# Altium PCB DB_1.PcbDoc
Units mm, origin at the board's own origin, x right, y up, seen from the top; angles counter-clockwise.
Board outline 57.15 x 76.2 mm, 4 copper layers (Top Layer, Signal Layer 1, Ground, Bottom Layer), stack 0.778 mm thick; 61 components, 63 nets, 348 pads, 125 vias.
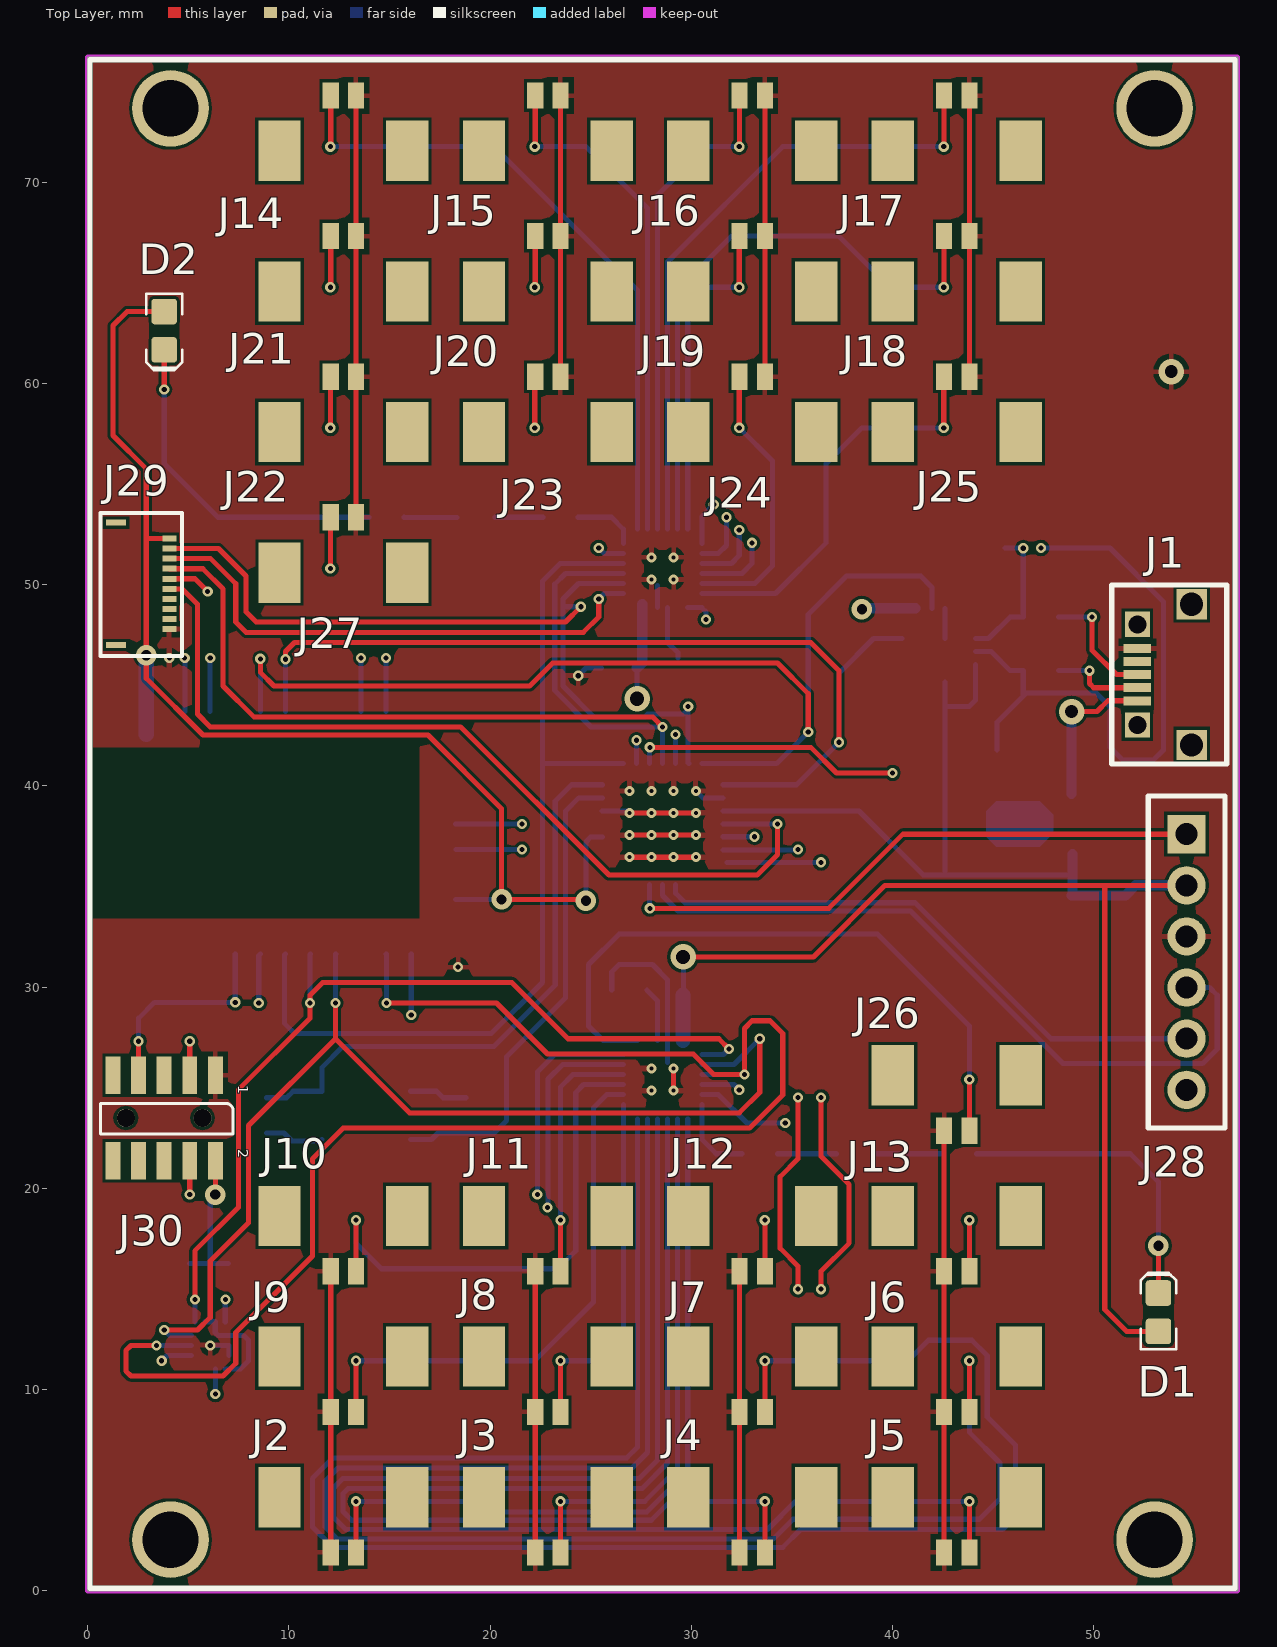
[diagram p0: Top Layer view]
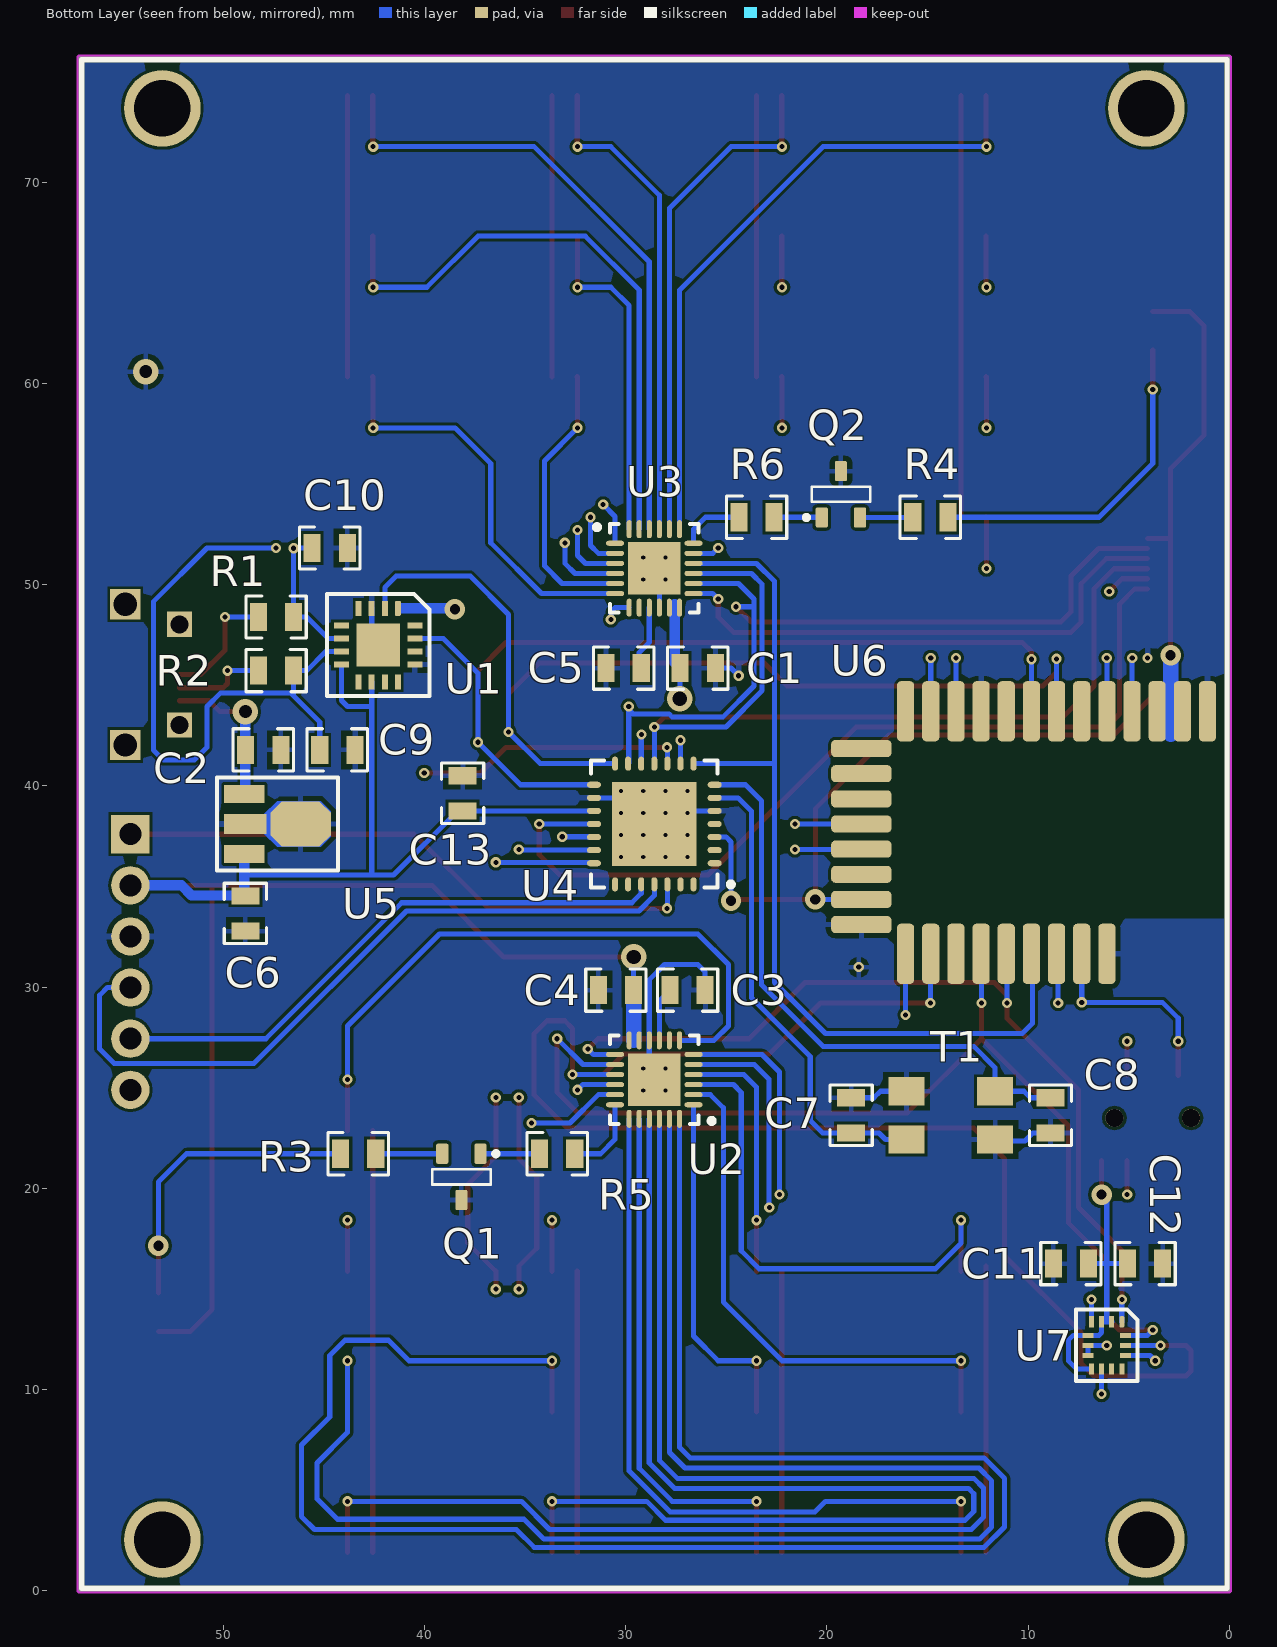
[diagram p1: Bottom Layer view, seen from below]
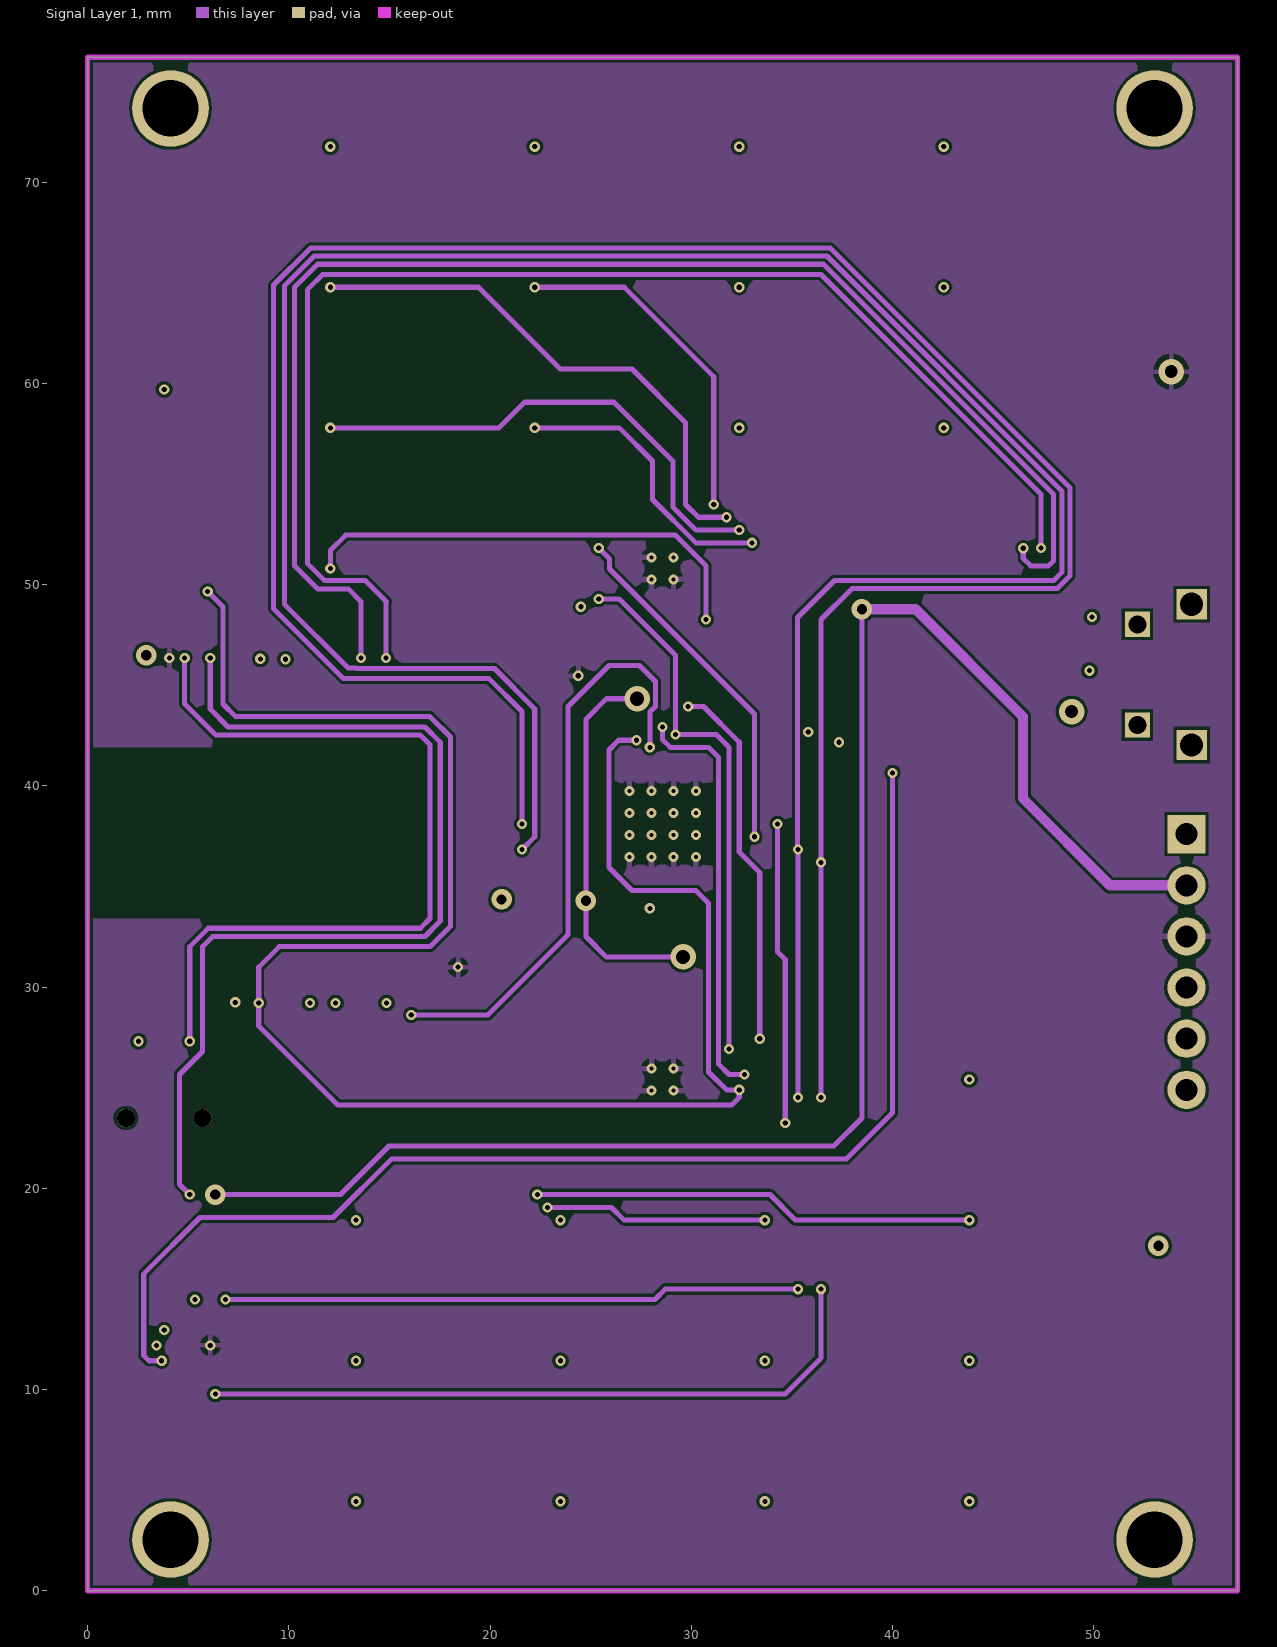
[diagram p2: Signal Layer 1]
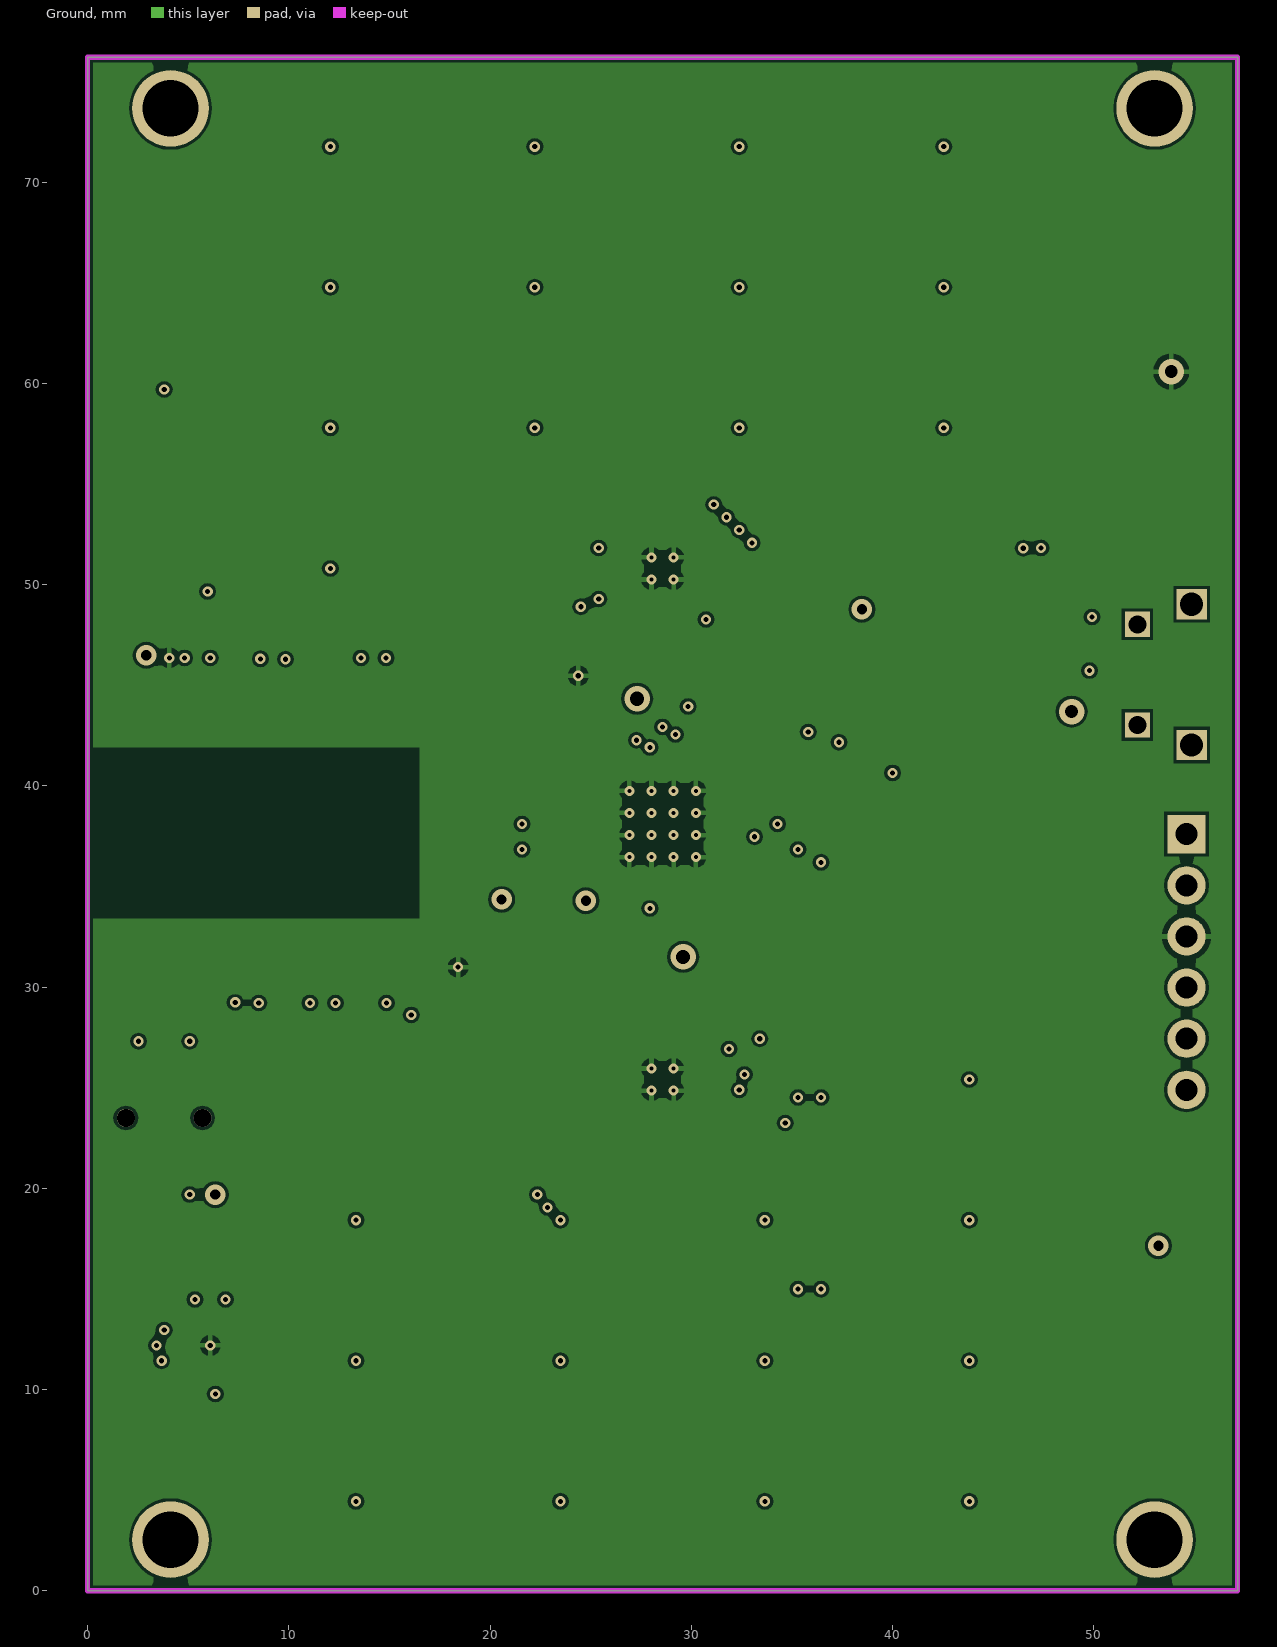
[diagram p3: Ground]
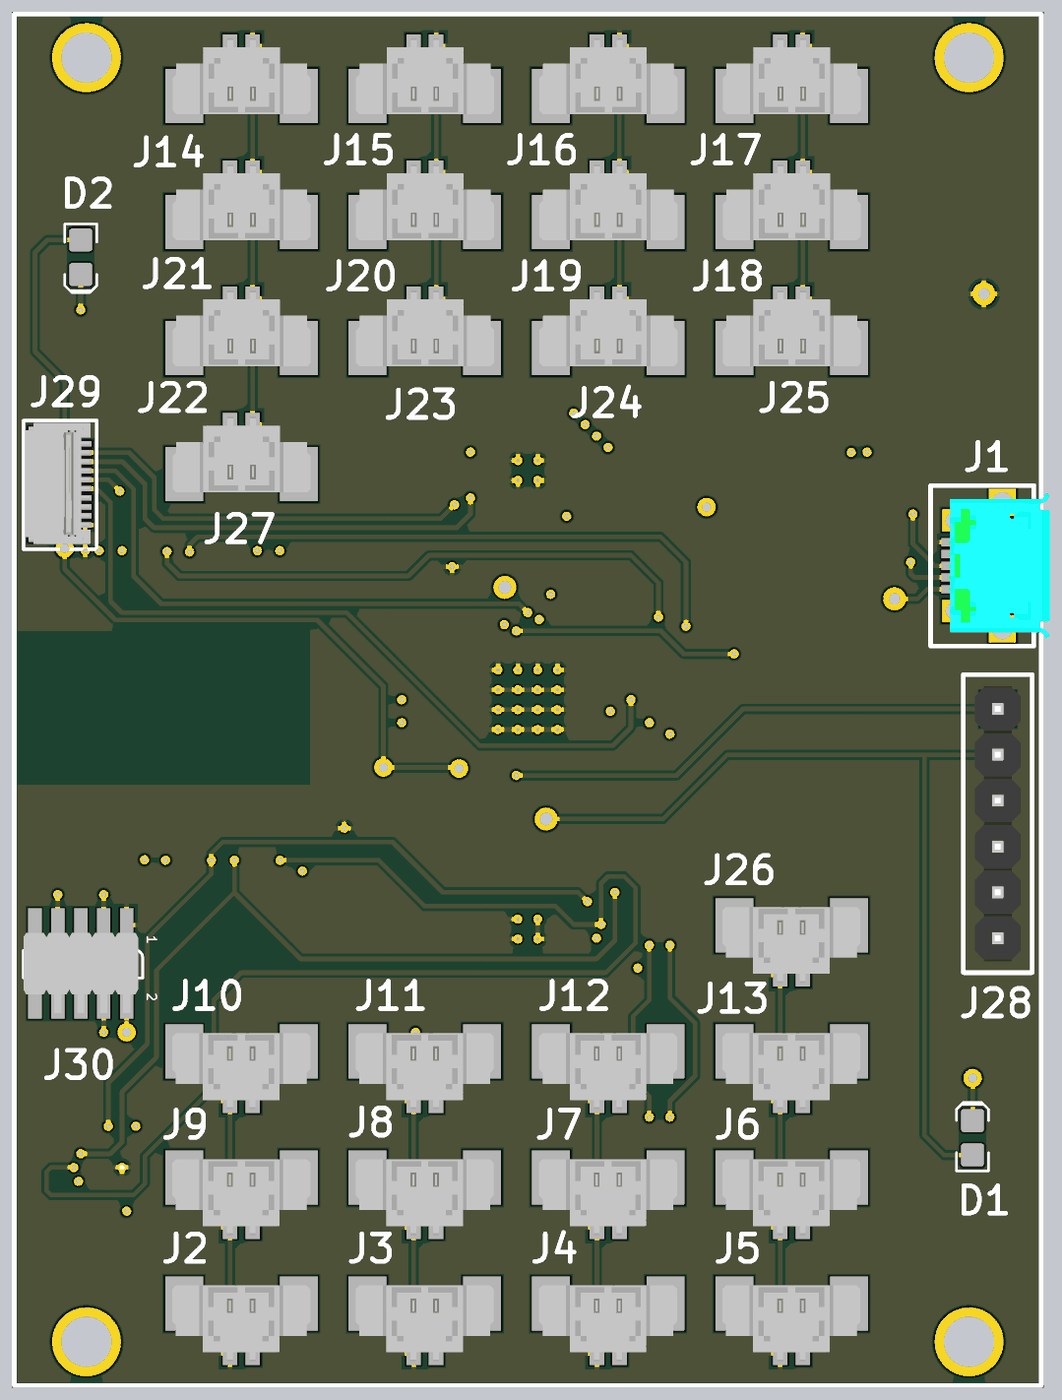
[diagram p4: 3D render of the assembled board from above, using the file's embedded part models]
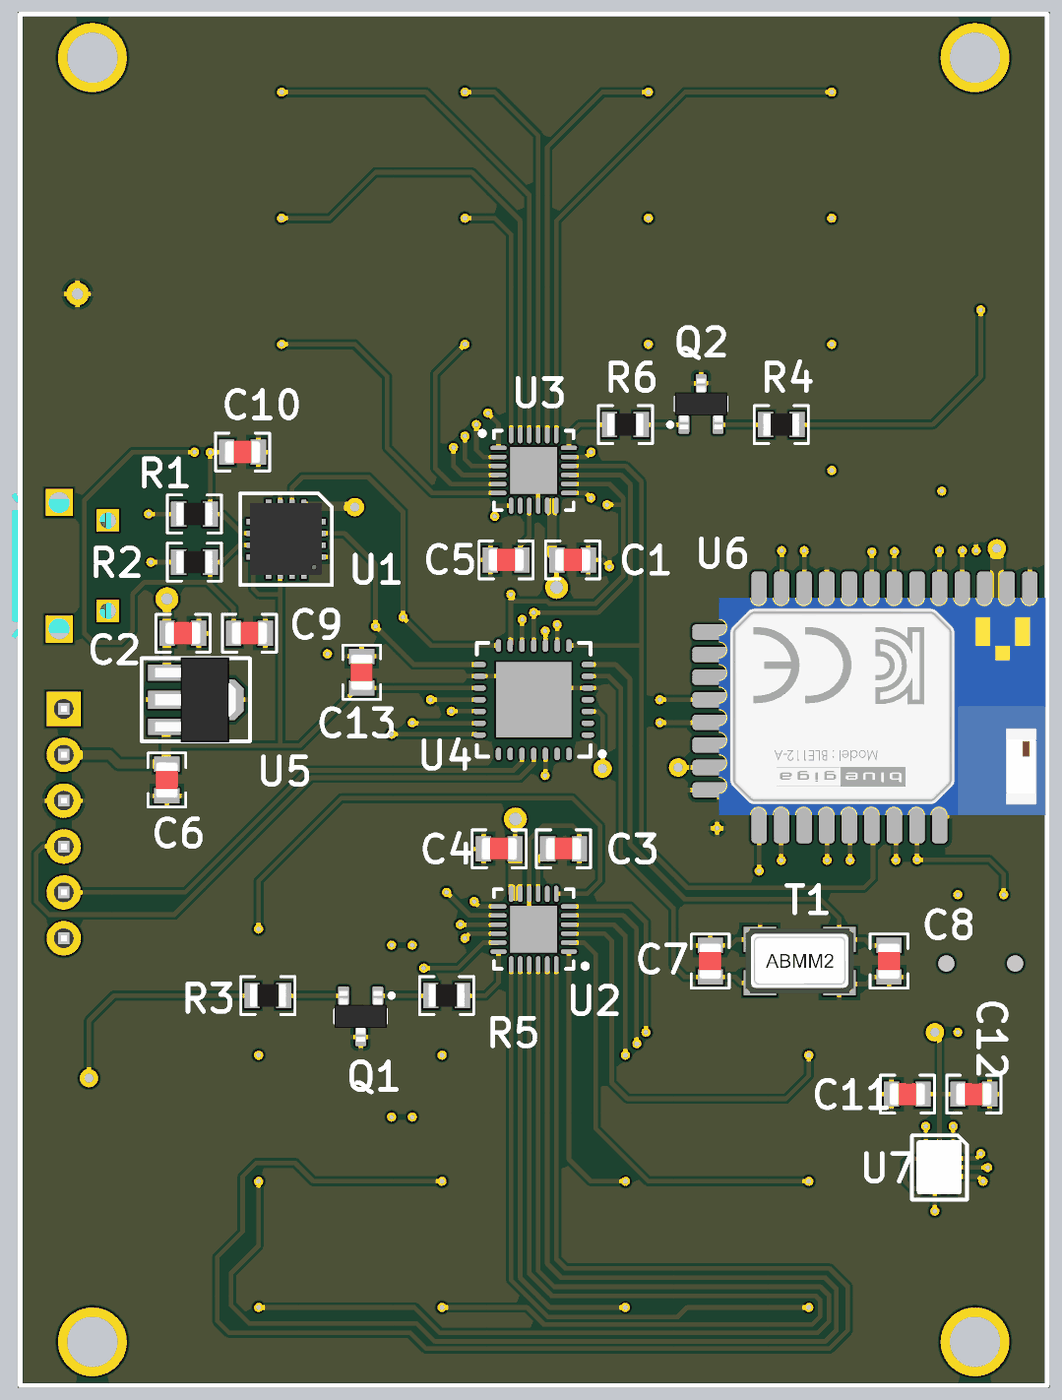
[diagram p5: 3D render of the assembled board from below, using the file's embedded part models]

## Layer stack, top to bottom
Top Solder: solder mask 0.0102, Solder Resist, Dk 3.5
Top Layer: signal copper 0.0356
Dielectric 1: core 0.254, FR-4, Dk 4.2
Signal Layer 1: signal copper 0.036
Dielectric 3: prepreg 0.127, Dk 4.2
Ground: signal copper 0.036
Dielectric 2: core 0.254, Dk 4.2
Bottom Layer: signal copper 0.0356
Bottom Solder: solder mask 0.0102, Solder Resist, Dk 3.5

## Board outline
0,0 57.15,0 57.15,76.2 0,76.2

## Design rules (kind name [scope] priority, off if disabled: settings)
Clearance [All] p1: gap=0.152
HoleSize [All] p1: absolutevalues=TRUE maxlimit=5.08 minlimit=0.025 maxpercent=80.000 minpercent=20.000
HoleToHoleClearance [All] p1: gap=0.152 allowstackedmicrovias=TRUE
MinimumSolderMaskSliver [All] p1: minsoldermaskwidth=0.152
PolygonConnect [All] p1: connectstyle=Relief reliefconductorwidth=0.254 reliefentries=4 polygonreliefangle="90 Angle" airgapwidth=0.254
RoutingVias [All] p1: holewidth=0.711 width=1.27 viastyle="Through Hole" minholewidth=0.203 minwidth=0.406 maxholewidth=0.711 maxwidth=1.27
SilkToSilkClearance [All] p1: silktosilkclearance=0.152
SilkToSolderMaskClearance [IsPad] p1: minsilkscreentomaskgap=0.152 clearancetoexposedcopper=TRUE
SolderMaskExpansion [All] p1: expansion=0.102
Width [All] p1: maxlimit=1.27 minlimit=0.152 preferedwidth=0.254
25 further rules are at their usual default settings.

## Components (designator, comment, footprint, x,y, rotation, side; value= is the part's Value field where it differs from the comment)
C1 "0.1µF" CAP-0805(2012)-R 26.416,45.847 r180 bottom
C2 "0.33µF" CAP-0805(2012)-R 48.006,41.783 r180 bottom
C3 "10000pF" CAP-0805(2012)-R 26.924,29.845 r180 bottom
C4 "0.1µF" CAP-0805(2012)-R 30.48,29.845 r0 bottom
C5 "10000pF" CAP-0805(2012)-R 30.099,45.847 r0 bottom
C6 "0.1µF" CAP-0805(2012)-R 48.895,33.655 r270 bottom
C7 "18pF" CAP-0805(2012)-R 18.796,23.622 r90 bottom
C8 "18pF" CAP-0805(2012)-R 8.89,23.622 r270 bottom
C9 "47pF" CAP-0805(2012)-R 44.323,41.783 r0 bottom
C10 "47pF" CAP-0805(2012)-R 44.704,51.816 r0 bottom
C11 "0.1µF" CAP-0805(2012)-R 7.874,16.256 r180 bottom
C12 "10000pF" CAP-0805(2012)-R 4.191,16.256 r0 bottom
C13 "0.1µF" CAP-0805(2012)-R 38.1,39.624 r90 bottom
D1 "YELLOW" LED-0805-A 53.213,13.843 r90 top
D2 "YELLOW" LED-0805-A 3.81,62.611 r270 top
J1 "USB" USB_CONNECTOR_5P_MICRO_USB_FCI 52.164,45.522 r90 top
J2 "Header 2 pin" WM7606CT-ND 13.335,1.905 r180 top
J3 "Header 2 pin" WM7606CT-ND 23.495,1.905 r180 top
J4 "Header 2 pin" WM7606CT-ND 33.655,1.905 r180 top
J5 "Header 2 pin" WM7606CT-ND 43.815,1.905 r180 top
J6 "Header 2 pin" WM7606CT-ND 43.815,8.89 r180 top
J7 "Header 2 pin" WM7606CT-ND 33.655,8.89 r180 top
J8 "Header 2 pin" WM7606CT-ND 23.495,8.89 r180 top
J9 "Header 2 pin" WM7606CT-ND 13.335,8.89 r180 top
J10 "Header 2 pin" WM7606CT-ND 13.335,15.875 r180 top
J11 "Header 2 pin" WM7606CT-ND 23.495,15.875 r180 top
J12 "Header 2 pin" WM7606CT-ND 33.655,15.875 r180 top
J13 "Header 2 pin" WM7606CT-ND 43.815,15.875 r180 top
J14 "Header 2 pin" WM7606CT-ND 12.085,74.295 r0 top
J15 "Header 2 pin" WM7606CT-ND 22.245,74.295 r0 top
J16 "Header 2 pin" WM7606CT-ND 32.405,74.295 r0 top
J17 "Header 2 pin" WM7606CT-ND 42.565,74.295 r0 top
J18 "Header 2 pin" WM7606CT-ND 42.565,67.31 r0 top
J19 "Header 2 pin" WM7606CT-ND 32.405,67.31 r0 top
J20 "Header 2 pin" WM7606CT-ND 22.245,67.31 r0 top
J21 "Header 2 pin" WM7606CT-ND 12.085,67.31 r0 top
J22 "Header 2 pin" WM7606CT-ND 12.085,60.325 r0 top
J23 "Header 2 pin" WM7606CT-ND 22.245,60.325 r0 top
J24 "Header 2 pin" WM7606CT-ND 32.405,60.325 r0 top
J25 "Header 2 pin" WM7606CT-ND 42.565,60.325 r0 top
J26 "Header 2 pin" WM7606CT-ND 43.815,22.86 r180 top
J27 "Header 2 pin" WM7606CT-ND 12.085,53.34 r0 top
J28 "Header 6 pin" HEADER-6-100MIL 54.61,37.592 r270 top
J29 "Header 10 pin" MOLEX-503480-1000 4.064,52.284 r270 top
J30 "GRPB052VWQP-RC" GRPB052VWQP-RC 1.27,25.616 r270 top
Q1 "Value" SOT23-3 38.161,20.567 r90 bottom
Q2 "Value" SOT23-3 19.304,54.483 r270 bottom
R1 "27" R-0805(2012)-R 47.371,48.387 r180 bottom
R2 "27" R-0805(2012)-R 47.371,45.72 r180 bottom
R3 "30" R-0805(2012)-R 43.293,21.717 r0 bottom
R4 "30" R-0805(2012)-R 14.859,53.34 r180 bottom
R5 "1k" R-0805(2012)-R 33.401,21.717 r180 bottom
R6 "1k" R-0805(2012)-R 23.495,53.34 r180 bottom
T1 "8MHz" CRYSTAL-8MHZ 13.843,23.622 r180 bottom
U1 "FT230XQ-R" QFN-16 42.291,46.99 r270 bottom
U2 "ADI-AD7147" LFCSP_WQ 28.575,25.4 r0 bottom
U3 "ADI-AD7147" LFCSP_WQ 28.575,50.8 r180 bottom
U4 "PIC18F25K80" MCHP-QFN-S-MM28_N 28.575,38.1 r0 bottom
U5 "L78L33ACUTR" SOT89-3 47.295,38.1 r180 bottom
U6 "BLE112-A-V1" BLE112-A-V1 18.288,43.7 r270 bottom
U7 "LSM6DS3H" LGA-14 6.096,12.192 r270 bottom

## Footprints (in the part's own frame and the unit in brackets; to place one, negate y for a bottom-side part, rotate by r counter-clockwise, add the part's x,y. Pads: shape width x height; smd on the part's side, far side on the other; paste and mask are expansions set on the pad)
BLE112-A-V1 [mm] "CLASS 2 BLTOOTH 4.0 MODULE"
  rrect50% 3x0.85 smd: 1(0,17.2) 2(0,15.95) 3(0,14.7) 4(0,13.45) 5(0,12.2) 6(0,10.95) 7(0,9.7) 8(0,8.45) 9(0,7.2) 10(0,5.95) 11(0,4.7) 12(0,3.45) 13(0,2.2) 22(12.05,2.2) 23(12.05,3.45) 24(12.05,4.7) 25(12.05,5.95) 26(12.05,7.2) 27(12.05,8.45) 28(12.05,9.7) 29(12.05,10.95) 30(12.05,12.2)
  rrect50% 0.85x3 smd: 14(1.85,0) 15(3.1,0) 16(4.35,0) 17(5.6,0) 18(6.85,0) 19(8.1,0) 20(9.35,0) 21(10.6,0)
  body extent -0.06,-0.03 11.99,18.07, height 2.3
CAP-0805(2012)-R [mm] "Capacitor 0805(2012) Reflow"
  rect 0.85x1.4 smd: 1(-0.875,0) 2(0.875,0)
  silkscreen extent -1.5,-1.05 1.5,1.05, body extent -1,-0.63 1,0.63, height 0.78
CRYSTAL-8MHZ [mm] "ABRACON ABMM2-8.000MHZ-E2-T"
  rect 1.8x1.4 smd: 1(-2.2,-1.2) 2(-2.2,1.2) 2(2.2,-1.2) 3(2.2,1.2)
  body extent -3,-1.78 3,1.82, height 1.21
GRPB052VWQP-RC [mm] "CONN HEADER .050\" 10PS DL SMD AU"
  rect 1.85x0.74 smd: 1(0,5.08) 2(4.25,5.08) 3(0,3.81) 4(4.25,3.81) 5(0,2.54) 6(4.25,2.54) 7(0,1.27) 8(4.25,1.27) 9(0,0) 10(4.25,0)
  round 0.9 hole 0.9 unplated: 21(2.121,0.635) 22(2.121,4.445)
  silkscreen extent 1.4,-0.63 2.92,5.97, body extent -0.62,-0.63 4.88,5.72, height 4.1
HEADER-6-100MIL [mil] "100 mil spacing"
  rect 75x75 hole 43: 1(0,0)
  round 75 hole 43: 2(100,0) 3(200,0) 4(300,0) 5(400,0) 6(500,0)
  silkscreen extent -75,-75 575,75, body extent -50,-50 550,50, height 339
LED-0805-A [mil]
  round 20 on Mech14: 0(0,0)
  rrect25% 50x50 smd: A(-37.5,0) K(37.5,0)
  Top Layer pour cut-out: -15,30 15,30 15,-30 -15,-30
  silkscreen extent -72,-35 77,35, body extent -39,-25 39,25, height 31
LFCSP_WQ [mm] "QFN, 24-Leads, Body 4x4mm, Pitch 0.5mm, Thermal Pad 2.5x2.5mm, IPC Medium Density"
  oval 0.9x0.25 smd: 1(-1.95,1.25) 2(-1.95,0.75) 3(-1.95,0.25) 4(-1.95,-0.25) 5(-1.95,-0.75) 6(-1.95,-1.25) 13(1.95,-1.25) 14(1.95,-0.75) 15(1.95,-0.25) 16(1.95,0.25) 17(1.95,0.75) 18(1.95,1.25)
  oval 0.25x0.9 smd: 7(-1.25,-1.95) 8(-0.75,-1.95) 9(-0.25,-1.95) 10(0.25,-1.95) 11(0.75,-1.95) 12(1.25,-1.95) 19(1.25,1.95) 20(0.75,1.95) 21(0.25,1.95) 22(-0.25,1.95) 23(-0.75,1.95) 24(-1.25,1.95)
  rect 2.6x2.6 smd: 25(0,0)
  silkscreen extent -2.97,-2.2 2.2,2.2, body extent -2.05,-2.05 2.05,2.05, height 1
LGA-14 [mm] "LGA-14 2.5X3X0.86 14L"
  rrect50% 0.55x0.25 smd: 1(-1.175,0.75)
  rect 0.55x0.25 smd: 2(-1.175,0.25) 3(-1.175,-0.25) 4(-1.175,-0.75) 8(1.175,-0.75) 9(1.175,-0.25) 10(1.175,0.25) 11(1.175,0.75)
  rect 0.25x0.55 smd: 5(-0.5,-0.925) 6(0,-0.925) 7(0.5,-0.925) 12(0.5,0.925) 13(0,0.925) 14(-0.5,0.925)
  silkscreen extent -1.78,-1.52 1.78,1.52, body extent -1.52,-1.27 1.48,1.23, height 0.86
MCHP-QFN-S-MM28_N [mm] "QFN, 28-Leads, Body 6x6mm, Pitch 0.65mm, Thermal Pad 4.175x4.175mm, IPC Medium Density"
  oval 0.7x0.3 smd: 1(-3,1.95) 2(-3,1.3) 3(-3,0.65) 4(-3,0) 5(-3,-0.65) 6(-3,-1.3) 7(-3,-1.95) 15(3,-1.95) 16(3,-1.3) 17(3,-0.65) 18(3,0) 19(3,0.65) 20(3,1.3) 21(3,1.95)
  oval 0.3x0.7 smd: 8(-1.95,-3) 9(-1.3,-3) 10(-0.65,-3) 11(0,-3) 12(0.65,-3) 13(1.3,-3) 14(1.95,-3) 22(1.95,3) 23(1.3,3) 24(0.65,3) 25(0,3) 26(-0.65,3) 27(-1.3,3) 28(-1.95,3)
  rect 4.18x4.18 smd: 29(0,0)
  silkscreen extent -3.92,-3.15 3.15,3.15, body extent -3,-3 3,3, height 1
MOLEX-503480-1000 [mm] "FPC Connector, 10-Leads, Right Angle, Pitch 0.5 mm, Mated Height 1.0 mm, SMT"
  rect 0.3x0.7 smd: 1(0,0) 2(0.5,0) 3(1,0) 4(1.5,0) 5(2,0) 6(2.5,0) 7(3,0) 8(3.5,0) 9(4,0) 10(4.5,0)
  rect 0.3x1 smd: MP1(-0.79,-2.65) MP2(5.29,-2.65)
  silkscreen extent -1.27,-3.43 5.84,0.64, body extent -1.14,-3.32 5.56,0.28, height 1.88
QFN-16 [mm]
  rrect50% 0.75x0.3 smd: 1(-1.825,0.975)
  rect 0.75x0.3 smd: 2(-1.825,0.325) 3(-1.825,-0.325) 4(-1.825,-0.975) 9(1.825,-0.975) 10(1.825,-0.325) 11(1.825,0.325) 12(1.825,0.975)
  rect 0.3x0.75 smd: 5(-0.975,-1.825) 6(-0.325,-1.825) 7(0.325,-1.825) 8(0.975,-1.825) 13(0.975,1.825) 14(0.325,1.825) 15(-0.325,1.825) 16(-0.975,1.825)
  rect 2.15x2.15 smd: 17(0,0)
  silkscreen extent -2.54,-2.54 2.54,2.54, body extent -2,-2 2,2, height 0.92
R-0805(2012)-R [mm] "Resistor 0805(2012) Reflow"
  rect 0.85x1.4 smd: 1(-0.875,0) 2(0.875,0)
  silkscreen extent -1.5,-1.05 1.5,1.05, body extent -1,-0.62 1,0.63, height 0.5
SOT23-3 [mm] "SOT23, 3 pin"
  round 0.5 on Mech14: 0(0,0)
  rrect25% 1x0.6 smd: 1(1.15,-0.95) 2(-1.15,0) 3(1.15,0.95)
  silkscreen extent -0.38,-1.81 1.25,1.45, body extent -1.4,-1.45 1.4,1.45, height 1.29
SOT89-3 [mm] "JEDEC TO-243 option AA / SOT89"
  round 1 on Mech14: 0(0,0)
  rrect1% 2x0.9 smd: 1(-1.65,1.5) 3(-1.65,-1.5)
  rrect1% 2.1x1 smd: 2(-1.6,0)
  oct 3x2.25 smd: 2(1.15,0)
  Top Layer region: -0.7,-0.45 -0.025,-1.125 2.15,-1.125 2.65,-0.625 2.65,0.625 2.15,1.125 -0.025,1.125 -0.7,0.45
  silkscreen extent -3,-2.3 3,2.3, body extent -2.25,-2.35 2.2,2.35, height 1.69
USB_CONNECTOR_5P_MICRO_USB_FCI [mm] "USB_Connector_5P_MICRO_USB_FCI_TypeB"
  rect 0.45x1.35 smd: 1(-1.3,0) 2(-0.65,0) 3(0,0) 4(0.65,0) 5(1.3,0)
  rect 1.25x1.25 hole 0.9: 15(2.5,0) 16(-2.5,0)
  rect 1.5x1.5 hole 1.15: 18(-3.5,-2.7) 18(3.5,-2.7)
  silkscreen extent -4.44,-4.44 4.44,1.27, body extent -4.03,-5.33 4.02,0.25, height 2.73
WM7606CT-ND [mm]
  rect 2.1x3 smd: 0(-2.55,-2.75) 0(3.8,-2.75)
  rect 0.8x1.3 smd: 1(0,0) 2(1.25,0)
  body extent -3.19,-3.76 4.46,0.44, height 4.72

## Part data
C1 C2 C3 C4 C5 C6 C7 C8 C9 C10 C11 C12 C13: library part C-0805(2012), "___ OHM ___ mW 0805(2012) SMD"
D1 D2: library part LED_0805_YELLOW, "LED, 0805 SMD, YELLOW"
J1: "USB_Connector_5P_MICRO_USB_FCI"
J2 J3 J4 J5 J6 J7 J8 J9 J10 J11 J12 J13 J14 J15 J16 J17 J18 J19 J20 J21 J22 J23 J24 J25 J26 J27: library part CON-2Pin, "Header, 2 pin, .1 pitch"
J28: library part CON-6Pin-100Mil, "Header, 6 pin, .1 pitch"
J29: library part WM1389CT-ND, "Header, 10 pin, .50mm pitch"
J30: "CONN HEADER .050\" 10PS DL SMD AU"
Q1 Q2: library part FMMT591CT-ND, "Transistor PNP"
R1 R2 R3 R4 R5 R6: library part R-0805(2012), "___ OHM ___ mW 0805(2012) SMD"
T1: library part CRYSTAL_8MHz, "Oscillator Crystal 8MHz 10ppm"
U1: "USB to Basic UART Interface Chip, UHCI/OHCI/EHCI Compatible, USB 2.0 Compatible, -40 to +85 degC, 16-Pin QFN, Pb-Free, Tape and Reel"
U6: "CLASS 2 BLTOOTH 4.0 MODULE"
U7: "3D accelerometer and 3D gyroscope"

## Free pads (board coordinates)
  round 3.81 hole 2.794: 0(4.127,2.54) 0(4.127,73.66) 0(53.023,2.54) 0(53.023,73.66)

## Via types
v1: diameter 0.508, hole 0.254, Top Layer to Bottom Layer, 91 vias
v2: diameter 0.5, hole 0.2, Top Layer to Bottom Layer, 24 vias
v3: diameter 1.016, hole 0.508, Top Layer to Bottom Layer, 6 vias
v4: diameter 1.27, hole 0.635, Top Layer to Bottom Layer, 2 vias
v5: diameter 1.27, hole 0.711, Top Layer to Bottom Layer, 2 vias

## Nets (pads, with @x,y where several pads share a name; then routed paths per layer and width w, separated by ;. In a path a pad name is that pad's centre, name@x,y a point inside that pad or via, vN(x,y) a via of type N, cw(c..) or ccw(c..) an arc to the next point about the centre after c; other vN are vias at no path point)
3.3V: C1.1 C4.1 C6.1 C11.2 C12.2 C13.1 D1.A D2.A J28.2 J29.1 J30.2 U1.1 U1.8 U1.10 U2.11 U2.12 U3.11 U3.12 U4.3 U4.17 U5.3 U6.2 U6.3 U6.20 U7.2 U7.3 U7.5 U7.8 | length 280.3
  Top Layer w0.254: D2.A 1.968,63.563 1.27,62.865 1.27,57.404 2.921,55.753 2.921,52.324 ; J29.1 2.961,52.284 2.921,52.324 ; v3(6.35,19.685) J30.2 ; v3(24.765,34.29) 24.705,34.35 v3(20.574,34.35) 20.574,38.862 16.916,42.52 5.74,42.52 2.921,45.339 v3(2.921,46.482) 2.921,52.324 ; v5(29.591,31.496) 36.068,31.496 39.624,35.052 50.546,35.052 ; D1.A 51.625,12.89 50.546,13.97 50.546,35.052 ; J28.2 50.546,35.052
  Signal Layer 1 w0.254: v3(6.35,19.685) 12.573,19.685 14.986,22.098 37.084,22.098 38.481,23.495 v3(38.481,48.768) ; v5(27.305,44.323) 25.781,44.323 24.765,43.307 v3(24.765,34.29) 24.765,32.512 25.781,31.496 v5(29.591,31.496)
  Signal Layer 1 w0.508: v3(38.481,48.768) 41.148,48.768 46.482,43.434 46.482,39.37 50.8,35.052 J28.2
  Bottom Layer w0.254: C12.2 6.096,16.256 ; U7.2 6.096,13.367 ; v3(6.35,19.685) 6.096,19.431 6.096,16.256 ; U7.8 7.588,11.017 8.001,11.43 8.001,12.446 7.755,12.692 U7.5 6.485,12.692 6.346,12.831 U7.3 6.096,13.367 ; C11.2 6.096,16.256 ; U6.20 v3(20.574,34.35) ; v3(24.765,34.29) 24.765,37.211 25.004,37.45 U4.3 ; v5(27.305,44.323) C1.1@27.305,45.833 ; v5(29.591,31.496) 29.605,31.482 C4.1 ; U4.17 38.339,38.75 41.529,35.56 48.945,35.56 ; 42.616,35.631 U1.10 ; 42.616,43.942 43.815,43.942 44.116,44.243 U1.8 ; 6.096,13.367 6.096,16.256
  Bottom Layer w0.508: C1.1 27.559,46.115 27.559,49.022 ; v3(38.481,48.768) 38.528,48.815 41.148,48.815 ; C6.1@48.895,34.544 51.562,34.544 52.07,35.052 J28.2 ; C6.1@48.945,34.594 48.945,35.56 U5.3
  Bottom Layer w0.762: 2.921,42.545 v3(2.921,46.482) ; 29.591,27.35 C4.1@29.591,29.591
A_INT1: U4.20 U6.18 U7.4 | length 170.7
  Top Layer w0.254: v1(35.306,14.986) 35.306,16.129 34.417,17.018 34.417,20.574 35.306,21.463 v1(35.306,24.511)
  Signal Layer 1 w0.254: v1(6.858,14.478) 28.194,14.478 28.702,14.986 v1(35.306,14.986) ; v1(21.59,36.83) 22.225,37.465 22.225,43.815 20.218,45.822 13.368,45.822 13.343,45.847 12.954,45.847 9.779,49.022 9.779,64.837 11.262,66.319 36.738,66.319 48.412,54.645 48.412,50.606 48.006,50.2 37.119,50.2 35.281,48.362 v1@35.281,36.855 ; v1(35.306,24.511) v1(35.306,36.83)
  Bottom Layer w0.254: U7.4 v1@6.846,14.466 ; U6.18@18.308,36.83 v1(21.59,36.83) ; U4.20 v1@35.276,36.8
A_INT2: U4.21 U6.17 U7.9 | length 176.9
  Top Layer w0.254: v1(36.449,14.986) 36.449,15.875 37.846,17.272 37.846,20.193 36.449,21.59 v1(36.449,24.511)
  Signal Layer 1 w0.254: v1(6.35,9.779) 34.671,9.779 36.449,11.557 v1(36.449,14.986) ; v1(21.59,38.1) 21.59,43.688 19.939,45.339 12.7,45.339 9.246,48.793 9.246,64.878 11.093,66.726 36.906,66.726 48.819,54.813 48.819,50.438 48.174,49.793 37.982,49.793 36.449,48.26 v1(36.449,36.195) v1(36.449,24.511)
  Bottom Layer w0.254: v1(6.35,9.779) U7.9@6.35,11.013 ; U6.17 v1(21.59,38.1) ; U4.21@31.784,36.195 v1(36.449,36.195)
CLK_IN: C7.1 T1.1 U4.6 | length 23.9
  Bottom Layer w0.254: T1.1 17.088,22.422 17.413,22.747 C7.1 20.207,22.747 20.828,23.368 20.828,26.543 23.749,29.464 23.749,38.735 24.414,39.4 U4.6
CLK_OUT: C8.1 T1.3 U4.7 | length 29.2
  Bottom Layer w0.254: C8.1 9.892,24.497 10.217,24.822 T1.3 11.643,25.994 12.7,27.051 20.193,27.051 23.241,30.099 23.241,39.243 24.048,40.05 U4.7
CS1: J29.5 U2.16 U4.9 U6.28 | length 97.8
  Top Layer w0.254: J29.5 5.342,50.284 v1(5.969,49.657)
  Signal Layer 1 w0.254: v1(5.969,49.657) 6.731,48.895 6.731,44.069 7.366,43.434 17.018,43.434 18.034,42.418 18.034,33.02 17.018,32.004 9.525,32.004 8.509,30.988 v1(8.509,29.21) 8.509,28.067 12.446,24.13 32.004,24.13 32.385,24.511 v1(32.385,24.892) 31.75,24.892 30.861,25.781 30.861,34.163 30.226,34.798 27.051,34.798 25.908,35.941 25.908,41.783 26.386,42.261 v1(27.275,42.261)
  Bottom Layer w0.254: v1(8.509,29.21) 8.509,31.571 U6.28 ; U4.9 v1(27.275,42.261) ; U2.16 32.127,25.15 v1(32.385,24.892)
CS2: U3.16 U4.8 U6.27 | length 45.9
  Bottom Layer w0.254: U6.27 9.779,31.591 9.779,29.21 9.779,28.194 10.287,27.686 20.066,27.686 22.606,30.226 22.606,41.1 ; U4.8 22.606,41.1 ; U3.16 23.491,51.05 22.606,50.165 22.606,41.1
CS3: U4.10 U6.22 U7.12 | length 110.2
  Top Layer w0.254: v1(27.94,41.91) 35.941,41.91 37.211,40.64 v1(40.005,40.64)
  Signal Layer 1 w0.254: v1(3.683,11.43) 3.048,11.43 2.794,11.684 2.794,15.748 5.588,18.542 12.192,18.542 15.113,21.463 37.719,21.463 40.005,23.749 v1(40.005,40.64) ; v1(16.088,28.616) 19.898,28.616 23.876,32.594 23.876,43.942 25.908,45.974 27.432,45.974 28.219,45.187 28.219,43.944 27.94,43.665 v1(27.94,41.91)
  Bottom Layer w0.254: v1(3.683,11.43) 3.945,11.692 U7.12 ; v1(16.088,28.616) U6.22 ; U4.10 27.925,41.895 v1(27.94,41.91)
GND: C1.2 C2.2 C3.2 C4.2 C5.2 C6.2 C7.2 C8.2 C9.1 C10.1 C11.1 C12.1 C13.2 J1.5 J2.2 J3.2 J4.2 J5.2 J6.2 J7.2 J8.2 J9.2 J10.2 J11.2 J12.2 J13.2 J14.2 J15.2 J16.2 J17.2 J18.2 J19.2 J20.2 J21.2 J22.2 J23.2 J24.2 J25.2 J26.2 J27.2 J28.3 J29.10 J30.1 Q1.2 Q2.2 T1.2 U1.3 U1.13 U1.17 U2.10 U2.25 U3.10 U3.25 U4.5 U4.16 U4.29 U5.2 U6.1 U6.10 U6.21 U6.30 U7.6 U7.7 | length 159.3
  Top Layer w0.254: J2.2 J9.2 J10.2@12.085,16.129 ; J27.2 J22.2 J21.2 J14.2 ; J3.2 J8.2 J11.2 ; J23.2 J20.2 J15.2 ; v2(26.925,36.45) v2(28.025,36.45) v2(29.125,36.45) v2(30.225,36.45) ; v2(26.925,37.55) v2(28.025,37.55) v2(29.125,37.55) v2(30.225,37.55) ; v2(26.925,38.65) v2(28.025,38.65) v2(29.125,38.65) v2(30.225,38.65) ; v2(29.125,24.85) v2(29.125,25.95) ; J4.2 J7.2 J12.2 ; J24.2 J19.2 J16.2 ; J5.2 J6.2 J13.2 J26.2 ; J25.2 J18.2 J17.2
  Bottom Layer w0.254: v1(6.096,12.192) U7.6 U7.7 ; C8.2 9.765,22.747 10.16,22.352 11.573,22.352 T1.2@11.643,22.422 ; T1.2@16.043,24.822 17.342,24.822 17.667,24.497 C7.2 ; v1(24.384,45.466) 24.765,45.847 C1.2 ; U4.5 26.825,38.75 v2(26.925,38.65) ; C3.2 26.049,30.748 26.416,31.115 28.067,31.115 28.825,30.357 U2.10 U2.25@28.825,26.25 ; U3.10 U3.25@28.325,49.95 ; v2(30.225,39.75) 30.575,39.4 U4.16 ; U1.17@42.616,47.315 U1.3
  other v1: 18.415,30.988 4.064,46.355
  other v2: 28.025,24.85 28.025,25.95 26.925,39.75 28.025,39.75 29.125,39.75 28.025,50.25 29.125,50.25 28.025,51.35 29.125,51.35
  other v4: 53.848,60.579
ICSPCLK: J28.5 U4.24 | length 28.8
  Bottom Layer w0.254: U4.24 29.225,34.656 29.693,34.188 41.123,34.188 47.879,27.432 J28.5
ICSPDAT: J28.4 U4.25 | length 36.2
  Bottom Layer w0.254: U4.25 28.575,34.544 29.337,33.782 40.894,33.782 48.476,26.2 55.41,26.2 56.134,26.924 56.134,29.591 55.753,29.972 J28.4
INT_1: J29.6 U2.17 U4.18 | length 63.7
  Top Layer w0.254: J29.6 4.699,49.784 5.461,49.022 5.461,43.561 6.096,42.926 18.542,42.926 25.908,35.56 33.274,35.56 34.29,36.576 v1(34.29,38.1)
  Signal Layer 1 w0.254: v1(34.29,38.1) 34.29,31.75 34.671,31.369 v1(34.671,23.241)
  Bottom Layer w0.254: U2.17 31.357,24.65 32.766,23.241 v1(34.671,23.241) ; U4.18 v1(34.29,38.1)
INT_2: U3.17 U4.19 | length 20.5
  Signal Layer 1 w0.254: v1(25.4,51.816) 25.933,51.283 25.933,50.775 33.147,43.561 v1(33.147,37.465)
  Bottom Layer w0.254: v1(25.4,51.816) 25.666,51.55 U3.17 ; U4.19 31.59,37.465 v1(33.147,37.465)
MCLR: J28.1 U4.26 | length 29.4
  Top Layer w0.254: v1(27.94,33.909) 36.83,33.909 40.513,37.592 J28.1
  Bottom Layer w0.254: U4.26 27.925,33.924 v1(27.94,33.909)
MISO: J29.3 U2.13 U3.13 U4.12 U6.26 U7.1 | length 99.7
  Top Layer w0.254: J29.3 6.12,51.284 7.366,50.038 7.366,48.133 7.874,47.625 24.638,47.625 25.4,48.387 v1(25.4,49.276) ; v1(5.334,14.478) 5.334,16.891 7.493,19.05 7.493,24.892 11.049,28.448 v1(11.049,29.21) 11.049,29.591 11.684,30.226 21.082,30.226 23.876,27.432 31.369,27.432 v1(31.877,26.924)
  Signal Layer 1 w0.254: v1(25.4,49.276) 26.416,49.276 29.21,46.482 v1(29.21,42.545) 31.242,42.545 31.877,41.91 v1(31.877,26.924)
  Bottom Layer w0.254: U7.1 v1@5.346,14.466 ; v1(11.049,29.21) 11.049,31.611 U6.26 ; v1(25.4,49.276) 25.674,49.55 U3.13 ; v1(29.21,42.545) 29.225,42.53 U4.12 ; U2.13 31.603,26.65 v1(31.877,26.924)
MOSI: J29.2 U2.14 U3.14 U4.13 U6.25 U7.14 | length 114.3
  Top Layer w0.254: v1(3.81,12.954) 5.461,12.954 6.096,13.589 6.096,16.383 8.001,18.288 8.001,23.114 12.319,27.432 ; J29.2 6.509,51.784 7.874,50.419 7.874,48.641 8.382,48.133 23.749,48.133 v1(24.511,48.895) ; v1(12.319,29.21) 12.319,27.432 ; v1(33.401,27.432) 33.401,24.765 32.385,23.749 16.002,23.749 12.319,27.432
  Signal Layer 1 w0.254: v1(29.845,43.942) 30.607,43.942 32.385,42.164 32.385,36.703 33.401,35.687 v1(33.401,27.432)
  Bottom Layer w0.254: v1(3.81,12.954) 4.072,12.692 U7.14 ; v1(12.319,29.21) 12.319,31.631 U6.25 ; 23.876,48.895 23.622,48.895 ; v1(24.511,48.895) 23.622,48.895 ; U3.14 24.396,50.05 23.622,49.276 23.622,48.895 ; U4.13 29.845,41.13 v1(29.845,43.942) 29.845,43.785 29.621,43.561 27.836,43.561 27.684,43.409 25.171,43.409 23.622,44.958 23.622,48.895 ; U2.14 32.119,26.15 v1(33.401,27.432)
NetC3_1: C3.1 U2.9 | length 2.7
  Bottom Layer w0.254: C3.1 28.321,29.323 28.321,27.354 U2.9
NetC5_1: C5.1 U3.9 | length 2.7
  Bottom Layer w0.254: U3.9 28.825,47.121 29.337,46.609 C5.1@29.337,46.341
NetD1_K: D1.K R3.2 | length 15.1
  Top Layer w0.254: D1.K v3(53.213,17.145)
  Bottom Layer w0.254: R3.2 51.816,21.717 53.213,20.32 v3(53.213,17.145)
NetD2_K: D2.K R4.2 | length 16.9
  Top Layer w0.254: v1(3.81,59.69) D2.K
  Bottom Layer w0.254: v1(3.81,59.69) 3.81,56.007 6.477,53.34 R4.2
NetJ1_2: J1.2 R2.1 | length 4.6
  Top Layer w0.254: v1(49.784,45.72) 49.784,45.085 49.997,44.872 J1.2
  Bottom Layer w0.254: R2.1 v1(49.784,45.72)
NetJ1_3: J1.3 R1.1 | length 6.1
  Top Layer w0.254: v1(49.911,48.387) 49.911,46.736 51.125,45.522 J1.3
  Bottom Layer w0.254: R1.1 v1(49.911,48.387)
NetQ1_1: Q1.1 R5.1 | length 2.9
  Bottom Layer w0.254: R5.1 Q1.1
NetQ1_3: Q1.3 R3.1 | length 3.3
  Bottom Layer w0.254: Q1.3 R3.1
NetQ2_1: Q2.1 R6.2 | length 2.4
  Bottom Layer w0.254: Q2.1 20.261,53.34 R6.2
NetQ2_3: Q2.3 R4.1 | length 2.6
  Bottom Layer w0.254: R4.1 15.741,53.333 Q2.3
NetR5_2: R5.2 U2.18 | length 4
  Bottom Layer w0.254: U2.18 30.525,22.434 31.242,21.717 R5.2
NetR6_1: R6.1 U3.18 | length 3.2
  Bottom Layer w0.254: R6.1 26.035,53.34 26.625,52.75 U3.18
P2_1: J30.4 U6.5 | length 53.2
  Top Layer w0.254: v1(5.08,19.685) J30.4
  Signal Layer 1 w0.254: v1(5.08,19.685) 4.572,20.193 4.572,25.654 5.715,26.797 5.715,32.004 6.223,32.512 16.764,32.512 17.526,33.274 17.526,42.164 16.764,42.926 6.985,42.926 6.096,43.815 v1(6.096,46.355)
  Bottom Layer w0.254: U6.5 6.088,46.347 v1(6.096,46.355)
P2_2: J30.3 U6.4 | length 45.5
  Top Layer w0.254: J30.3 v1(5.08,27.305)
  Signal Layer 1 w0.254: v1(4.826,46.355) 4.826,44.069 6.375,42.52 16.535,42.52 17.018,42.037 17.018,33.401 16.535,32.918 5.994,32.918 5.08,32.004 v1(5.08,27.305)
  Bottom Layer w0.254: v1(4.826,46.355) 4.838,46.343 U6.4
RESET: J30.7 U6.29 | length 10.4
  Top Layer w0.254: J30.7 v1(2.54,27.305)
  Bottom Layer w0.254: v1(2.54,27.305) 2.54,28.448 3.33,29.238 v1(7.338,29.238) U6.29
RX: U1.15 U4.15 U6.8 | length 48.7
  Top Layer w0.254: v1(9.838,46.287) 9.838,46.668 10.287,47.117 35.941,47.117 37.338,45.72 v1(37.338,42.164)
  Bottom Layer w0.254: U6.8 v1(9.838,46.287) ; U4.15 35.224,40.05 v1(37.338,42.164) 37.338,45.593 39.06,47.315 U1.15
S1: J2.1 U2.19 | length 37.6
  Top Layer w0.254: J2.1 v1(13.335,4.445)
  Bottom Layer w0.254: v1(13.335,4.445) 20.066,4.445 20.599,3.912 27.788,3.912 29.825,5.949 U2.19
S2: J3.1 U2.20 | length 26.4
  Top Layer w0.254: J3.1 v1(23.495,4.445)
  Bottom Layer w0.254: v1(23.495,4.445) 27.686,4.445 29.325,6.084 U2.20
S3: J4.1 U2.21 | length 58.8
  Top Layer w0.254: J4.1 v1(33.655,4.445)
  Bottom Layer w0.254: U2.21 28.825,6.346 27.559,5.08 12.954,5.08 12.7,4.826 12.7,3.937 13.132,3.505 28.016,3.505 28.956,4.445 v1(33.655,4.445)
S4: J5.1 U2.22 | length 70.1
  Top Layer w0.254: J5.1 v1(43.815,4.445)
  Bottom Layer w0.254: U2.22 28.325,6.481 27.432,5.588 12.7,5.588 12.217,5.105 12.217,3.658 12.827,3.048 33.782,3.048 35.179,4.445 v1(43.815,4.445)
S5: J6.1 U2.23 | length 80.1
  Top Layer w0.254: J6.1 v1(43.815,11.43)
  Bottom Layer w0.254: U2.23 27.825,6.87 27.051,6.096 12.446,6.096 11.811,5.461 11.811,3.175 12.421,2.565 34.061,2.565 35.052,3.556 44.323,3.556 45.339,4.572 45.339,6.35 43.815,7.874 v1(43.815,11.43)
S6: J7.1 U2.24 | length 94.4
  Top Layer w0.254: J7.1 v1(33.655,11.43)
  Bottom Layer w0.254: U2.24 27.325,7.132 26.797,6.604 12.192,6.604 11.176,5.588 11.176,3.175 12.192,2.159 34.544,2.159 35.433,3.048 45.466,3.048 46.101,3.683 46.101,7.239 44.704,8.636 44.704,11.684 43.942,12.446 41.783,12.446 40.767,11.43 v1(33.655,11.43)
S7: J8.1 U2.1 | length 17.7
  Top Layer w0.254: J8.1 v1(23.495,11.43)
  Bottom Layer w0.254: v1(23.495,11.43) 25.4,11.43 26.625,12.655 U2.1
S8: J9.1 U2.2 | length 27
  Top Layer w0.254: J9.1 v1(13.335,11.43)
  Bottom Layer w0.254: v1(13.335,11.43) 22.225,11.43 25.146,14.351 25.146,24.003 25.793,24.65 U2.2
S9: J10.1 U2.3 | length 25.9
  Top Layer w0.254: J10.1 v1(13.335,18.415)
  Bottom Layer w0.254: v1(13.335,18.415) 13.335,17.272 14.605,16.002 23.368,16.002 24.257,16.891 24.257,24.765 24.642,25.15 U2.3
S10: J11.1 U2.4 | length 12.5
  Top Layer w0.254: J11.1 v1(23.495,18.415)
  Bottom Layer w0.254: v1(23.495,18.415) 23.495,25.019 24.126,25.65 U2.4
S11: J12.1 U2.5 | length 24
  Top Layer w0.254: J12.1 v1(33.655,18.415)
  Signal Layer 1 w0.254: v1(22.86,19.05) 26.035,19.05 26.67,18.415 v1(33.655,18.415)
  Bottom Layer w0.254: v1(22.86,19.05) 22.885,19.075 22.885,25.425 23.61,26.15 U2.5
S12: J13.1 U2.6 | length 35.3
  Top Layer w0.254: J13.1 v1(43.815,18.415)
  Signal Layer 1 w0.254: v1(22.352,19.685) 33.909,19.685 35.179,18.415 v1(43.815,18.415)
  Bottom Layer w0.254: v1(22.352,19.685) 22.352,25.781 23.221,26.65 U2.6
S13: J14.1 U3.19 | length 32.6
  Top Layer w0.254: v1(12.065,71.755) 12.085,71.775 J14.1
  Bottom Layer w0.254: v1(12.065,71.755) 20.193,71.755 27.325,64.623 U3.19
S14: J15.1 U3.20 | length 25.4
  Top Layer w0.254: v1(22.225,71.755) 22.245,71.775 J15.1
  Bottom Layer w0.254: v1(22.225,71.755) 24.765,71.755 27.825,68.695 U3.20
S15: J16.1 U3.21 | length 24.2
  Top Layer w0.254: v1(32.385,71.755) 32.405,71.775 J16.1
  Bottom Layer w0.254: U3.21 28.325,69.346 30.734,71.755 v1(32.385,71.755)
S16: J17.1 U3.22 | length 31.9
  Top Layer w0.254: v1(42.545,71.755) 42.565,71.775 J17.1
  Bottom Layer w0.254: U3.22 28.825,66.05 ; 28.839,66.05 34.544,71.755 v1(42.545,71.755)
S17: J18.1 U3.23 | length 29.8
  Top Layer w0.254: v1(42.545,64.77) 42.565,64.79 J18.1
  Bottom Layer w0.254: U3.23 29.325,64.631 32.004,67.31 37.338,67.31 39.878,64.77 v1(42.545,64.77)
S18: J19.1 U3.24 | length 16.6
  Top Layer w0.254: v1(32.385,64.77) 32.385,67.29 J19.1
  Bottom Layer w0.254: U3.24 29.825,63.861 30.734,64.77 v1(32.385,64.77)
S19: J20.1 U3.1 | length 21.8
  Top Layer w0.254: v1(22.225,64.77) 22.245,64.79 J20.1
  Signal Layer 1 w0.254: v1(22.225,64.77) 26.67,64.77 31.115,60.325 v1(31.115,53.975)
  Bottom Layer w0.254: U3.1 30.525,53.385 v1(31.115,53.975)
S20: J21.1 U3.2 | length 32.1
  Top Layer w0.254: v1(12.065,64.77) 12.085,64.79 J21.1
  Signal Layer 1 w0.254: v1(12.065,64.77) 19.431,64.77 23.495,60.706 27.051,60.706 29.718,58.039 29.718,53.975 30.353,53.34 v1(31.75,53.34)
  Bottom Layer w0.254: U3.2 31.357,51.55 31.75,51.943 v1(31.75,53.34)
S21: J22.1 U3.3 | length 30.7
  Top Layer w0.254: v1(12.065,57.785) 12.065,60.305 J22.1
  Signal Layer 1 w0.254: v1(12.065,57.785) 20.447,57.785 21.717,59.055 26.162,59.055 29.083,56.134 29.083,53.848 30.226,52.705 v1(32.385,52.705)
  Bottom Layer w0.254: U3.3 32,51.05 32.385,51.435 v1(32.385,52.705)
S22: J23.1 U3.4 | length 20.5
  Top Layer w0.254: v1(22.225,57.785) 22.225,60.305 J23.1
  Signal Layer 1 w0.254: v1(22.225,57.785) 26.416,57.785 28.067,56.134 28.067,54.229 30.226,52.07 v1(33.02,52.07)
  Bottom Layer w0.254: U3.4 32.516,50.55 33.02,51.054 v1(33.02,52.07)
S23: J24.1 U3.5 | length 14
  Top Layer w0.254: v1(32.385,57.785) 32.385,60.305 J24.1
  Bottom Layer w0.254: U3.5 33.159,50.05 34.036,50.927 34.036,56.134 v1(32.385,57.785)
S24: J25.1 U3.6 | length 20.3
  Top Layer w0.254: v1(42.545,57.785) 42.545,60.305 J25.1
  Bottom Layer w0.254: U3.6 34.183,49.55 36.703,52.07 36.703,56.007 38.481,57.785 v1(42.545,57.785)
S25: J26.1 U2.7 | length 32.4
  Top Layer w0.254: J26.1 v1(43.815,25.4)
  Bottom Layer w0.254: U2.7 25.609,27.35 24.892,28.067 24.892,31.115 26.416,32.639 39.243,32.639 43.815,28.067 v1(43.815,25.4)
S26: J27.1 U3.7 | length 27.1
  Top Layer w0.254: v1(12.065,50.8) 12.065,53.32 J27.1
  Signal Layer 1 w0.254: v1(12.065,50.8) 12.065,51.689 12.827,52.451 29.21,52.451 30.734,50.927 v1(30.734,48.26)
  Bottom Layer w0.254: U3.7 30.525,48.85 30.734,48.641 v1(30.734,48.26)
SCLK: J29.4 U2.15 U3.15 U4.11 U6.23 U7.13 | length 146.1
  Top Layer w0.254: v1(3.429,12.192) 2.159,12.192 1.905,11.938 1.905,10.922 2.159,10.668 6.731,10.668 7.366,11.303 7.366,12.827 11.176,16.637 11.176,21.463 12.7,22.987 32.893,22.987 34.544,24.638 34.544,27.686 33.909,28.321 33.02,28.321 32.639,27.94 v1(32.639,25.654) 31.115,25.654 30.099,26.67 22.86,26.67 20.32,29.21 v1(14.859,29.21) ; J29.4 5.731,50.784 6.731,49.784 6.731,44.958 8.28,43.409 28.092,43.409 v1(28.575,42.926)
  Signal Layer 1 w0.254: v1(28.575,42.926) 28.575,42.291 28.956,41.91 30.861,41.91 31.344,41.427 31.344,26.187 31.877,25.654 v1(32.639,25.654)
  Bottom Layer w0.254: v1(3.429,12.192) U7.13 ; U6.23 14.859,31.629 v1(14.859,29.21) ; 24.638,50.546 23.749,50.546 23.216,50.013 23.216,44.729 25.019,42.926 v1(28.575,42.926) U4.11 ; 24.638,50.55 U3.15 ; U2.15 32.635,25.65 v1(32.639,25.654)
TX: U1.2 U4.14 U6.7 | length 53.8
  Top Layer w0.254: v1(8.588,46.307) 8.588,45.641 9.271,44.958 21.971,44.958 23.114,46.101 34.29,46.101 35.814,44.577 v1(35.814,42.672)
  Bottom Layer w0.254: U6.7 v1(8.588,46.307) ; U4.14 34.242,41.1 v1(35.814,42.672) 35.814,48.514 37.719,50.419 41.402,50.419 41.966,49.855 U1.2
USB_D+: C10.2 R1.2 U1.6 U6.11 | length 79
  Signal Layer 1 w0.254: v1(13.589,46.355) 13.589,49.149 12.954,49.784 11.43,49.784 10.287,50.927 10.287,64.77 11.43,65.913 36.57,65.913 48.006,54.477 48.006,51.181 47.752,50.927 46.863,50.927 46.496,51.294 v1(46.496,51.802)
  Bottom Layer w0.254: U6.11 v1(13.589,46.355) ; v1(13.589,46.355) v1(13.589,46.355) ; U1.6 44.775,47.315 45.847,48.387 R1.2 v1(46.496,51.802) 46.482,51.816 C10.2
USB_D-: C9.2 R2.2 U1.7 U6.12 | length 99.3
  Signal Layer 1 w0.254: v1(14.838,46.355) 14.838,49.128 14.859,49.149 13.818,50.19 11.786,50.19 10.922,51.054 10.922,64.643 11.684,65.405 36.449,65.405 47.371,54.483 v1(47.371,51.816)
  Bottom Layer w0.254: U6.12 v1(14.838,46.355) ; U1.7 44.902,46.665 45.847,45.72 R2.2 46.496,44.464 ; C9.2 45.198,43.166 46.496,44.464 ; v1(47.371,51.816) 50.8,51.816 53.467,49.149 53.467,41.783 52.959,41.275 51.435,41.275 50.8,41.91 50.8,43.942 50.14,44.602 46.634,44.602 46.496,44.464
V_USB: C2.1 J1.1 U5.1 | length 7.6
  Top Layer w0.254: v4(48.895,43.688) 50.165,43.688 50.699,44.222 J1.1
  Bottom Layer w0.508: U5.1@48.895,39.6 v4(48.895,43.688)
pads on no net: D1.0 D2.0 J1.4 J1.15 J1.16 J1.18 J2.0 J3.0 J4.0 J5.0 J6.0 J7.0 J8.0 J9.0 J10.0 J11.0 J12.0 J13.0 J14.0 J15.0 J16.0 J17.0 J18.0 J19.0 J20.0 J21.0 J22.0 J23.0 J24.0 J25.0 J26.0 J27.0 J28.6 J29.7 J29.8 J29.9 J29.MP1 J29.MP2 J30.5 J30.6 J30.8 J30.9 J30.10 J30.21 J30.22 Q1.0 Q2.0 U1.4 U1.5 U1.9 U1.11 U1.12 U1.14 U1.16 U2.8 U3.8 U4.1 U4.2 U4.4 U4.22 U4.23 U4.27 U4.28 U5.0 U6.6 U6.9 U6.13 U6.14 U6.15 U6.16 U6.19 U6.24 U7.10 U7.11

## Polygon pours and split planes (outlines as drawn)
GND on Ground "Top_Layer-GND" (solid, remove dead copper, pour order 0): 0.254,0.254 56.896,0.254 56.896,75.946 0.254,75.946 0.254,0.254
GND on Bottom Layer "Top_Layer-GND" (solid, remove dead copper, pour order 2): 0.254,0.254 56.896,0.254 56.896,75.946 0.254,75.946 0.254,0.254
GND on Top Layer "Top_Layer-GND" (solid, remove dead copper, pour order 4): 0.254,0.254 56.896,0.254 56.896,75.946 0.254,75.946 0.254,0.254
GND on Signal Layer 1 "Signal_Layer-GND" (solid, remove dead copper, pour order 6): 0.254,0.254 56.896,0.254 56.896,75.946 0.254,75.946 0.254,0.254

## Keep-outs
Keep-Out Layer:
  the board outline again, w0.254

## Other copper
Top Layer:
  pour cut-out: 0,41.91 16.51,41.91 16.51,33.401 0,33.401
Signal Layer 1:
  pour cut-out: 0,41.91 16.51,41.91 16.51,33.401 0,33.401
Ground:
  pour cut-out: 0,41.91 16.51,41.91 16.51,33.401 0,33.401
Bottom Layer:
  pour cut-out: 0,41.91 16.51,41.91 16.51,33.401 0,33.401

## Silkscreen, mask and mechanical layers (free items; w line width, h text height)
Top Overlay:
  lines w0.254: 0.127,0.127 0.127,76.073 57.023,76.073 57.023,0.127 0.127,0.127
Bottom Overlay:
  lines w0.254: 0.127,0.127 57.023,0.127 57.023,76.073 0.127,76.073 0.127,0.127
Mechanical 3:
  the board outline again, w0.254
